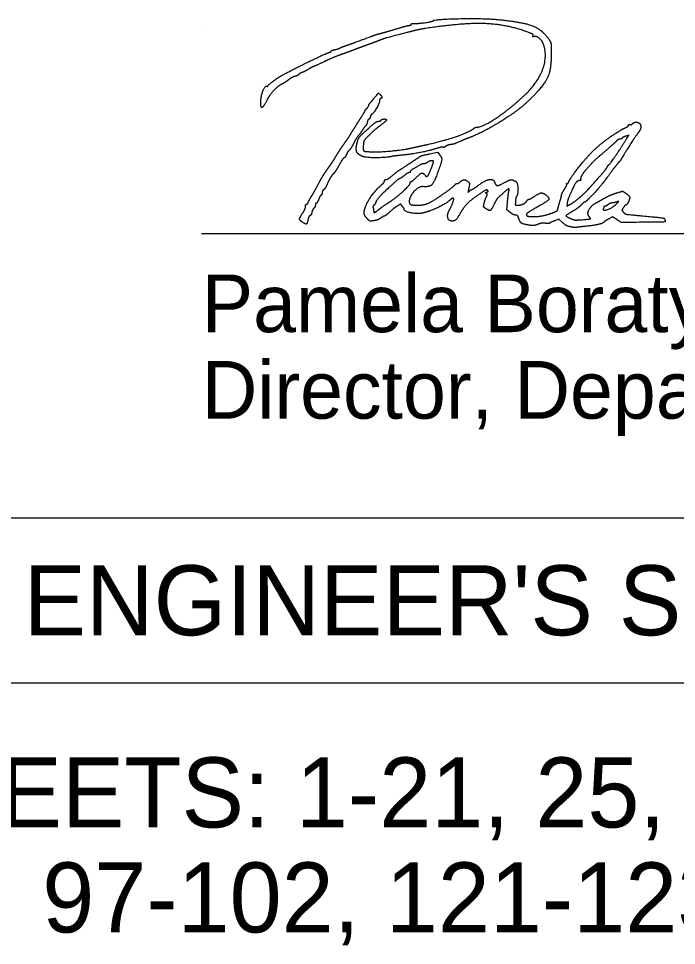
# Model space of a CAD drawing. Extents: x -21.9 to 47.3, y 14.1 to 48.7.
# Drawn here: x 24.055 to 25.653, y 33.195 to 35.446 of the extents above; entities that cross this region are included whole.
import ezdxf

# ---------------------------------------------------------------- set-up
doc = ezdxf.new("R2010")
doc.units = 0
for name, color, linetype in [('GM_X_City_Street', 7, 'Continuous'), ('SH_Data', 7, 'Continuous'), ('SH_Text', 7, 'Continuous')]:
    doc.layers.add(name, color=color, linetype=linetype)

msp = doc.modelspace()

# ---------------------------------------------------------------- linework, layer by layer
at = {"layer": 'GM_X_City_Street'}
for points in [[(25.5318, 35.1539), (25.5372, 35.1628), (25.5298, 35.1602)], [(25.0545, 35.1177), (25.0725, 35.1218), (25.0772, 35.1156)], [(25.2494, 34.9749), (25.2411, 34.9812), (25.2426, 34.9983)], [(25.3874, 34.9969), (25.3864, 34.9904), (25.3951, 34.9949)], [(25.3764, 34.9506), (25.3672, 34.9589), (25.3567, 34.9548)], [(25.5083, 34.9576), (25.4976, 34.9644), (25.4892, 34.9599)]]:
    msp.add_lwpolyline(points, dxfattribs=at)
for points in [[(24.9721, 35.4207), (24.9882, 35.4255), (25.0031, 35.4294), (25.0051, 35.4294)], [(25.0051, 35.4294), (25.0072, 35.4294), (25.0089, 35.4305), (25.0089, 35.4318)], [(25.0089, 35.4318), (25.0089, 35.4332), (25.0129, 35.4342), (25.0179, 35.4341)], [(25.0179, 35.4341), (25.0275, 35.4338), (25.0585, 35.4382), (25.0619, 35.4403)], [(25.2926, 35.4126), (25.242, 35.4316), (25.1341, 35.4356), (25.0437, 35.4218)], [(25.0619, 35.4403), (25.0687, 35.4445), (25.1857, 35.4468), (25.2201, 35.4434)], [(25.2201, 35.4434), (25.2794, 35.4375), (25.3269, 35.4193), (25.3427, 35.3962)], [(24.9093, 35.4017), (24.9172, 35.4047), (24.928, 35.4082), (24.9333, 35.4096)], [(24.9333, 35.4096), (24.9386, 35.4109), (24.9561, 35.4159), (24.9721, 35.4207)], [(24.9993, 35.4121), (24.9483, 35.3989), (24.944, 35.3977), (24.9333, 35.3934)], [(25.0437, 35.4218), (25.0345, 35.4204), (25.0145, 35.4161), (24.9993, 35.4121)], [(25.3049, 35.404), (25.3059, 35.4065), (25.3024, 35.4089), (25.2926, 35.4126)], [(25.3073, 35.4019), (25.3047, 35.4009), (25.304, 35.4016), (25.3049, 35.404)], [(25.3307, 35.382), (25.3274, 35.3918), (25.313, 35.4041), (25.3073, 35.4019)], [(24.8349, 35.374), (24.8362, 35.3749), (24.8443, 35.3782), (24.8529, 35.3811)], [(24.8529, 35.3811), (24.8676, 35.3862), (24.8741, 35.3886), (24.9093, 35.4017)], [(24.9105, 35.3849), (24.9006, 35.3813), (24.8855, 35.3757), (24.8769, 35.3725)], [(24.9333, 35.3934), (24.9307, 35.3923), (24.9204, 35.3885), (24.9105, 35.3849)], [(25.2852, 35.2608), (25.3161, 35.2902), (25.34, 35.3538), (25.3307, 35.382)], [(25.3427, 35.3962), (25.3476, 35.389), (25.3486, 35.3846), (25.3489, 35.3668)], [(24.6969, 35.309), (24.7271, 35.3252), (24.8007, 35.3608), (24.8091, 35.3633)], [(24.8409, 35.3593), (24.8297, 35.3554), (24.8093, 35.3468), (24.7957, 35.3403)], [(24.8091, 35.3633), (24.8121, 35.3642), (24.8145, 35.3658), (24.8145, 35.3668)], [(24.8145, 35.3668), (24.8145, 35.3679), (24.8185, 35.3696), (24.8235, 35.3705)], [(24.8235, 35.3705), (24.8284, 35.3714), (24.8336, 35.373), (24.8349, 35.374)], [(24.8769, 35.3725), (24.8683, 35.3692), (24.8521, 35.3633), (24.8409, 35.3593)], [(25.3489, 35.3668), (25.3496, 35.326), (25.3335, 35.2863), (25.3041, 35.2564)], [(24.7957, 35.3403), (24.782, 35.3338), (24.7704, 35.3286), (24.7698, 35.3286)], [(24.745, 35.3154), (24.7418, 35.3144), (24.7376, 35.312), (24.7358, 35.3102)], [(24.7598, 35.3229), (24.7549, 35.3198), (24.7482, 35.3164), (24.745, 35.3154)], [(24.7698, 35.3286), (24.7693, 35.3286), (24.7648, 35.326), (24.7598, 35.3229)], [(24.6609, 35.2823), (24.6609, 35.2845), (24.6863, 35.3033), (24.6969, 35.309)], [(24.7113, 35.2973), (24.7067, 35.2937), (24.6995, 35.2891), (24.6954, 35.287)], [(24.7261, 35.3054), (24.7226, 35.3045), (24.7159, 35.3009), (24.7113, 35.2973)], [(24.7358, 35.3102), (24.734, 35.3084), (24.7297, 35.3063), (24.7261, 35.3054)], [(24.6437, 35.2445), (24.6438, 35.2577), (24.6545, 35.2842), (24.6586, 35.2817)], [(24.6586, 35.2817), (24.6599, 35.2809), (24.6609, 35.2812), (24.6609, 35.2823)], [(24.6954, 35.287), (24.685, 35.2817), (24.6651, 35.2608), (24.6589, 35.2487)], [(24.6451, 35.2308), (24.6443, 35.2316), (24.6437, 35.2377), (24.6437, 35.2445)], [(24.6589, 35.2487), (24.6522, 35.2358), (24.6469, 35.2289), (24.6451, 35.2308)], [(24.9111, 35.2434), (24.9296, 35.2655), (24.9289, 35.265), (24.933, 35.2616)], [(24.9321, 35.2467), (24.9321, 35.2411), (24.9162, 35.2134), (24.913, 35.2134)], [(24.9345, 35.2518), (24.9332, 35.2518), (24.9321, 35.2495), (24.9321, 35.2467)], [(24.933, 35.2616), (24.9373, 35.258), (24.9382, 35.2518), (24.9345, 35.2518)], [(25.1685, 35.1822), (25.1826, 35.1822), (25.2507, 35.2281), (25.2852, 35.2608)], [(25.3041, 35.2564), (25.2855, 35.2375), (25.2531, 35.2126), (25.2226, 35.1938)], [(24.8881, 35.2073), (24.8937, 35.2159), (24.8977, 35.223), (24.8971, 35.223)], [(24.8971, 35.223), (24.8966, 35.223), (24.8983, 35.2251), (24.9009, 35.2278)], [(24.9009, 35.2278), (24.9035, 35.2304), (24.9057, 35.2335), (24.9057, 35.2347)], [(24.9057, 35.2347), (24.9057, 35.236), (24.9081, 35.2398), (24.9111, 35.2434)], [(24.8661, 35.1723), (24.8727, 35.1829), (24.8826, 35.1987), (24.8881, 35.2073)], [(24.9058, 35.2014), (24.9047, 35.2014), (24.903, 35.1981), (24.9021, 35.1942)], [(24.9095, 35.2074), (24.9087, 35.2041), (24.907, 35.2014), (24.9058, 35.2014)], [(24.913, 35.2134), (24.9119, 35.2134), (24.9103, 35.2107), (24.9095, 35.2074)], [(24.9357, 35.199), (24.9375, 35.2019), (24.9489, 35.2022), (24.9489, 35.1993)], [(24.8982, 35.1856), (24.8969, 35.1848), (24.8931, 35.1796), (24.8897, 35.1741)], [(24.8973, 35.1724), (24.913, 35.187), (24.9258, 35.1966), (24.9297, 35.1966)], [(24.9021, 35.1942), (24.9012, 35.1902), (24.8995, 35.1864), (24.8982, 35.1856)], [(24.9339, 35.1862), (24.9256, 35.1801), (24.9131, 35.1692), (24.9061, 35.1621)], [(24.9297, 35.1966), (24.9322, 35.1966), (24.9349, 35.1976), (24.9357, 35.199)], [(24.9489, 35.1993), (24.9489, 35.1982), (24.9421, 35.1923), (24.9339, 35.1862)], [(25.0485, 35.1402), (25.0854, 35.1484), (25.1517, 35.1713), (25.1603, 35.1788)], [(25.2226, 35.1938), (25.2035, 35.1819), (25.1622, 35.1609), (25.1481, 35.1558)], [(25.1603, 35.1788), (25.1624, 35.1807), (25.1661, 35.1822), (25.1685, 35.1822)], [(25.5001, 35.1638), (25.5191, 35.176), (25.5209, 35.1771), (25.5291, 35.1808)], [(25.5291, 35.1808), (25.5334, 35.1827), (25.5369, 35.1856), (25.5369, 35.1871)], [(25.5369, 35.1871), (25.5369, 35.1886), (25.5384, 35.1893), (25.5403, 35.1886)], [(25.5403, 35.1886), (25.5422, 35.1878), (25.545, 35.1888), (25.5466, 35.1907)], [(25.5466, 35.1907), (25.5482, 35.1926), (25.5519, 35.1942), (25.5548, 35.1942)], [(25.5548, 35.1942), (25.5643, 35.1942), (25.568, 35.1781), (25.5606, 35.1691)], [(24.8443, 35.1393), (24.8497, 35.1468), (24.8595, 35.1616), (24.8661, 35.1723)], [(24.8806, 35.1617), (24.8789, 35.1604), (24.8742, 35.1528), (24.8702, 35.1448)], [(24.876, 35.1378), (24.8787, 35.1508), (24.8849, 35.1608), (24.8973, 35.1724)], [(24.8897, 35.1741), (24.8863, 35.1686), (24.8822, 35.1631), (24.8806, 35.1617)], [(24.9061, 35.1621), (24.8954, 35.1511), (24.8932, 35.1474), (24.8927, 35.1392)], [(25.1481, 35.1558), (25.1435, 35.1542), (25.1364, 35.1514), (25.1325, 35.1496)], [(25.4055, 35.0712), (25.4278, 35.1021), (25.4728, 35.1461), (25.5001, 35.1638)], [(25.5212, 35.1555), (25.5204, 35.1543), (25.518, 35.1534), (25.5158, 35.1534)], [(25.5606, 35.1691), (25.5564, 35.1641), (25.5236, 35.1137), (25.5204, 35.1075)], [(25.5298, 35.1602), (25.5258, 35.1588), (25.5219, 35.1567), (25.5212, 35.1555)], [(24.8276, 35.1138), (24.8315, 35.1204), (24.839, 35.1319), (24.8443, 35.1393)], [(24.8702, 35.1448), (24.8662, 35.1368), (24.8611, 35.1288), (24.859, 35.127)], [(24.8913, 35.1109), (24.8809, 35.1148), (24.8737, 35.1273), (24.876, 35.1378)], [(24.8927, 35.1392), (24.8918, 35.1258), (24.8959, 35.1229), (24.9165, 35.1223)], [(24.9165, 35.1223), (24.9358, 35.1218), (24.9936, 35.1279), (25.0149, 35.1327)], [(25.0149, 35.1327), (25.0228, 35.1345), (25.0379, 35.1379), (25.0485, 35.1402)], [(25.0863, 35.1335), (25.0846, 35.1341), (25.0765, 35.1324), (25.0683, 35.1297)], [(25.0931, 35.1357), (25.091, 35.1339), (25.0879, 35.1329), (25.0863, 35.1335)], [(25.1039, 35.1397), (25.1, 35.1393), (25.0952, 35.1375), (25.0931, 35.1357)], [(25.1325, 35.1496), (25.1154, 35.1422), (25.1105, 35.1405), (25.1039, 35.1397)], [(25.507, 35.148), (25.5043, 35.145), (25.4918, 35.1339), (25.4793, 35.1234)], [(25.489, 35.091), (25.4918, 35.0929), (25.52, 35.1344), (25.5318, 35.1539)], [(25.5158, 35.1534), (25.5136, 35.1534), (25.5097, 35.1509), (25.507, 35.148)], [(24.8146, 35.0931), (24.8179, 35.0979), (24.8238, 35.1072), (24.8276, 35.1138)], [(24.8517, 35.1157), (24.8498, 35.1113), (24.8473, 35.1078), (24.846, 35.1078)], [(24.859, 35.127), (24.8568, 35.1252), (24.8535, 35.1201), (24.8517, 35.1157)], [(24.9625, 35.1111), (24.9488, 35.108), (24.8993, 35.1079), (24.8913, 35.1109)], [(24.9829, 35.1137), (24.9746, 35.1129), (24.9654, 35.1117), (24.9625, 35.1111)], [(25.0683, 35.1297), (25.0518, 35.1245), (25.0067, 35.116), (24.9829, 35.1137)], [(25.0005, 35.0913), (25.0322, 35.1123), (25.0335, 35.113), (25.0545, 35.1177)], [(25.0772, 35.1156), (25.0838, 35.1068), (25.0836, 35.102), (25.0759, 35.0794)], [(25.4793, 35.1234), (25.4597, 35.1069), (25.448, 35.0955), (25.4313, 35.0766)], [(24.801, 35.0739), (24.8051, 35.0797), (24.8112, 35.0884), (24.8146, 35.0931)], [(24.8339, 35.0902), (24.8286, 35.0805), (24.8219, 35.0705), (24.8191, 35.068)], [(24.846, 35.1078), (24.8447, 35.1078), (24.8393, 35.0998), (24.8339, 35.0902)], [(24.9613, 35.0634), (24.975, 35.0744), (24.973, 35.073), (25.0005, 35.0913)], [(25.0302, 35.0902), (25.0158, 35.0823), (25.0065, 35.0759), (25.0065, 35.0739)], [(25.0399, 35.0934), (25.0377, 35.0934), (25.0333, 35.0919), (25.0302, 35.0902)], [(25.0486, 35.0969), (25.0461, 35.0949), (25.0421, 35.0934), (25.0399, 35.0934)], [(25.0471, 35.0622), (25.0489, 35.0622), (25.0587, 35.0833), (25.0618, 35.094)], [(25.0585, 35.1005), (25.0557, 35.1004), (25.0512, 35.0988), (25.0486, 35.0969)], [(25.0618, 35.094), (25.0635, 35.0997), (25.0631, 35.1005), (25.0585, 35.1005)], [(25.4851, 35.0858), (25.4863, 35.088), (25.4881, 35.0903), (25.489, 35.091)], [(25.5118, 35.0953), (25.5088, 35.0921), (25.4999, 35.0808), (25.492, 35.0701)], [(25.5204, 35.1075), (25.5187, 35.104), (25.5148, 35.0986), (25.5118, 35.0953)], [(24.7821, 35.0418), (24.7884, 35.0536), (24.7969, 35.0681), (24.801, 35.0739)], [(24.8191, 35.068), (24.8162, 35.0654), (24.8107, 35.0563), (24.8068, 35.0478)], [(24.9921, 35.0646), (24.9871, 35.0606), (24.9821, 35.0573), (24.981, 35.0573)], [(25.0038, 35.0718), (25.0024, 35.0718), (24.9971, 35.0685), (24.9921, 35.0646)], [(25.0065, 35.0739), (25.0065, 35.0727), (25.0053, 35.0718), (25.0038, 35.0718)], [(25.0209, 35.0598), (25.031, 35.0699), (25.0376, 35.0717), (25.0425, 35.0658)], [(25.0759, 35.0794), (25.0656, 35.0495), (25.0537, 35.0364), (25.0377, 35.0378)], [(25.0425, 35.0658), (25.0441, 35.0638), (25.0462, 35.0622), (25.0471, 35.0622)], [(25.3905, 35.0479), (25.3905, 35.0493), (25.3972, 35.0598), (25.4055, 35.0712)], [(25.4313, 35.0766), (25.4255, 35.07), (25.4192, 35.0571), (25.4206, 35.0547)], [(25.4538, 35.048), (25.4691, 35.0651), (25.4827, 35.0815), (25.4851, 35.0858)], [(25.492, 35.0701), (25.4841, 35.0595), (25.4765, 35.0493), (25.475, 35.0475)], [(24.8068, 35.0478), (24.8029, 35.0392), (24.7981, 35.0313), (24.7963, 35.0302)], [(24.9006, 34.9955), (24.9051, 35.0059), (24.9283, 35.0354), (24.9387, 35.0437)], [(24.9387, 35.0437), (24.9417, 35.0461), (24.9441, 35.0496), (24.9441, 35.0515)], [(24.9441, 35.0515), (24.9441, 35.0534), (24.9456, 35.055), (24.9475, 35.055)], [(24.981, 35.0573), (24.9791, 35.0573), (24.9706, 35.0501), (24.9453, 35.0268)], [(24.9475, 35.055), (24.9493, 35.055), (24.9555, 35.0587), (24.9613, 35.0634)], [(24.9604, 35.0036), (24.976, 35.014), (25.0065, 35.0427), (25.0065, 35.047)], [(25.0065, 35.047), (25.0065, 35.0487), (25.0076, 35.0502), (25.0089, 35.0502)], [(25.0089, 35.0502), (25.0102, 35.0502), (25.0156, 35.0545), (25.0209, 35.0598)], [(25.0725, 35.0105), (25.0911, 35.0228), (25.1135, 35.0395), (25.1152, 35.0423)], [(25.1152, 35.0423), (25.1163, 35.044), (25.1186, 35.0454), (25.1204, 35.0454)], [(25.1204, 35.0454), (25.1223, 35.0454), (25.1255, 35.0471), (25.1277, 35.0493)], [(25.1277, 35.0493), (25.1326, 35.0542), (25.1426, 35.0543), (25.1475, 35.0493)], [(25.1475, 35.0493), (25.1507, 35.0462), (25.1509, 35.0437), (25.1488, 35.0346)], [(25.1657, 35.0367), (25.1859, 35.0519), (25.2086, 35.0575), (25.2116, 35.048)], [(25.2116, 35.048), (25.214, 35.0404), (25.2221, 35.0403), (25.2354, 35.0476)], [(25.2354, 35.0476), (25.2474, 35.0543), (25.2546, 35.055), (25.2628, 35.0504)], [(25.2628, 35.0504), (25.2672, 35.0479), (25.2689, 35.0199), (25.265, 35.0147)], [(25.3807, 35.0311), (25.3846, 35.0373), (25.3871, 35.0431), (25.3863, 35.0439)], [(25.3863, 35.0439), (25.3855, 35.0447), (25.3862, 35.0454), (25.3877, 35.0454)], [(25.3877, 35.0454), (25.3892, 35.0454), (25.3905, 35.0465), (25.3905, 35.0479)], [(25.4184, 35.0526), (25.412, 35.0526), (25.4025, 35.0374), (25.3904, 35.0082)], [(25.4206, 35.0547), (25.4214, 35.0535), (25.4204, 35.0526), (25.4184, 35.0526)], [(25.4382, 35.0305), (25.4413, 35.0341), (25.4484, 35.0419), (25.4538, 35.048)], [(25.475, 35.0475), (25.4617, 35.031), (25.4572, 35.0259), (25.4453, 35.0137)], [(24.7667, 35.0142), (24.7689, 35.0175), (24.7759, 35.0299), (24.7821, 35.0418)], [(24.7929, 35.0238), (24.7929, 35.0213), (24.7918, 35.0185), (24.7904, 35.0177)], [(24.7963, 35.0302), (24.7944, 35.0292), (24.7929, 35.0263), (24.7929, 35.0238)], [(24.9453, 35.0268), (24.9362, 35.0184), (24.9225, 35.0014), (24.9225, 34.9984)], [(25.0377, 35.0378), (25.0273, 35.0387), (25.0041, 35.0133), (25.0041, 35.001)], [(25.1741, 35.0194), (25.1544, 35.006), (25.1372, 34.9889), (25.1289, 34.9746)], [(25.1488, 35.0346), (25.1465, 35.0243), (25.1466, 35.0238), (25.1504, 35.0273)], [(25.1504, 35.0273), (25.1526, 35.0293), (25.1553, 35.031), (25.1562, 35.031)], [(25.1562, 35.031), (25.1572, 35.031), (25.1615, 35.0335), (25.1657, 35.0367)], [(25.1943, 35.0289), (25.1925, 35.0307), (25.1866, 35.0279), (25.1741, 35.0194)], [(25.1915, 35.0212), (25.1893, 35.0226), (25.1896, 35.0235), (25.1927, 35.0247)], [(25.1908, 35.0114), (25.1937, 35.0177), (25.1938, 35.0198), (25.1915, 35.0212)], [(25.1927, 35.0247), (25.1957, 35.0258), (25.1962, 35.0271), (25.1943, 35.0289)], [(25.2354, 35.0248), (25.2195, 35.0108), (25.2158, 35.0064), (25.2103, 34.995)], [(25.2455, 35.0232), (25.2474, 35.0326), (25.2447, 35.033), (25.2354, 35.0248)], [(25.2426, 34.9983), (25.2434, 35.0077), (25.2447, 35.0189), (25.2455, 35.0232)], [(25.3081, 35.0142), (25.321, 35.0224), (25.3286, 35.0232), (25.3363, 35.0171)], [(25.3737, 35.0163), (25.3737, 35.0181), (25.3769, 35.0248), (25.3807, 35.0311)], [(25.4181, 35.0117), (25.426, 35.0185), (25.4351, 35.027), (25.4382, 35.0305)], [(25.4781, 35.0097), (25.486, 35.0142), (25.4992, 35.0199), (25.5074, 35.0224)], [(25.5074, 35.0224), (25.5215, 35.0266), (25.5226, 35.0266), (25.5285, 35.0228)], [(25.5285, 35.0228), (25.5381, 35.0165), (25.5405, 35.0091), (25.5359, 35.0001)], [(24.7545, 34.995), (24.7559, 34.995), (24.7583, 34.9979), (24.7598, 35.0016)], [(24.7598, 35.0016), (24.7614, 35.0052), (24.7645, 35.0109), (24.7667, 35.0142)], [(24.7782, 34.9974), (24.7771, 34.9974), (24.7761, 34.9953), (24.7761, 34.9928)], [(24.7841, 35.0067), (24.7821, 35.0016), (24.7794, 34.9974), (24.7782, 34.9974)], [(24.7904, 35.0177), (24.789, 35.0168), (24.7862, 35.0119), (24.7841, 35.0067)], [(24.9225, 34.9984), (24.9225, 34.9976), (24.9208, 34.9953), (24.9188, 34.9933)], [(24.9289, 34.9812), (24.9364, 34.9873), (24.9417, 34.9911), (24.9604, 35.0036)], [(25.0041, 35.001), (25.0041, 34.9959), (25.0119, 34.9926), (25.024, 34.9926)], [(25.024, 34.9926), (25.0371, 34.9926), (25.0562, 34.9996), (25.0725, 35.0105)], [(25.1045, 35.0063), (25.0949, 34.9972), (25.0562, 34.9784), (25.0377, 34.9739)], [(25.1015, 34.9806), (25.1056, 34.9882), (25.1121, 35.0045), (25.1121, 35.0072)], [(25.1121, 35.0072), (25.1121, 35.0103), (25.1081, 35.0098), (25.1045, 35.0063)], [(25.1857, 34.9958), (25.1865, 34.9999), (25.1888, 35.007), (25.1908, 35.0114)], [(25.262, 35.0021), (25.2615, 34.9946), (25.2622, 34.9926), (25.2654, 34.9926)], [(25.265, 35.0147), (25.2637, 35.0131), (25.2624, 35.0074), (25.262, 35.0021)], [(25.2654, 34.9926), (25.2737, 34.9926), (25.2857, 34.9974), (25.289, 35.0021)], [(25.289, 35.0021), (25.2908, 35.0048), (25.2933, 35.007), (25.2945, 35.007)], [(25.2945, 35.007), (25.2957, 35.007), (25.3018, 35.0102), (25.3081, 35.0142)], [(25.3363, 35.0171), (25.346, 35.0095), (25.3391, 35.0016), (25.3076, 34.9839)], [(25.3654, 34.9851), (25.3661, 34.9885), (25.3683, 34.9962), (25.3702, 35.0022)], [(25.3702, 35.0022), (25.3721, 35.0081), (25.3737, 35.0145), (25.3737, 35.0163)], [(25.3904, 35.0082), (25.3893, 35.0055), (25.388, 35.0004), (25.3874, 34.9969)], [(25.3951, 34.9949), (25.3998, 34.9973), (25.4102, 35.0049), (25.4181, 35.0117)], [(25.4297, 34.9998), (25.4286, 34.9998), (25.4247, 34.9966), (25.4211, 34.9928)], [(25.4453, 35.0137), (25.4378, 35.006), (25.4308, 34.9998), (25.4297, 34.9998)], [(25.4415, 34.9643), (25.4354, 34.9717), (25.4452, 34.9915), (25.4585, 34.9987)], [(25.4585, 34.9987), (25.4614, 35.0002), (25.4702, 35.0052), (25.4781, 35.0097)], [(25.4975, 34.9983), (25.4936, 34.9978), (25.4887, 34.9957), (25.4865, 34.9937)], [(25.5093, 35.001), (25.5067, 35), (25.5013, 34.9988), (25.4975, 34.9983)], [(25.5069, 34.9955), (25.5124, 35.0011), (25.513, 35.0024), (25.5093, 35.001)], [(25.5359, 35.0001), (25.5337, 34.9959), (25.531, 34.9926), (25.5299, 34.9926)], [(24.7446, 34.9514), (24.7376, 34.9562), (24.7381, 34.9629), (24.7463, 34.9751)], [(24.7463, 34.9751), (24.7495, 34.9798), (24.7521, 34.9862), (24.7521, 34.9893)], [(24.7521, 34.9893), (24.7521, 34.9924), (24.7532, 34.995), (24.7545, 34.995)], [(24.7676, 34.9754), (24.7668, 34.9715), (24.7646, 34.9677), (24.7629, 34.967)], [(24.7727, 34.9855), (24.7708, 34.9839), (24.7685, 34.9794), (24.7676, 34.9754)], [(24.7761, 34.9928), (24.7761, 34.9904), (24.7745, 34.9871), (24.7727, 34.9855)], [(24.9023, 34.9598), (24.8947, 34.9674), (24.8941, 34.9802), (24.9006, 34.9955)], [(24.9188, 34.9933), (24.9167, 34.9912), (24.9156, 34.988), (24.9164, 34.986)], [(24.9164, 34.986), (24.9171, 34.9841), (24.9177, 34.981), (24.9177, 34.9792)], [(24.9177, 34.9792), (24.9177, 34.9743), (24.9211, 34.9749), (24.9289, 34.9812)], [(24.9762, 34.9914), (24.968, 34.986), (24.9654, 34.984), (24.9542, 34.974)], [(24.9875, 34.99), (24.983, 34.9958), (24.983, 34.9958), (24.9762, 34.9914)], [(24.992, 34.9826), (24.992, 34.9835), (24.99, 34.9868), (24.9875, 34.99)], [(25.0377, 34.9739), (25.0248, 34.9708), (24.9922, 34.977), (24.992, 34.9826)], [(25.1082, 34.9542), (25.0998, 34.9542), (25.0958, 34.97), (25.1015, 34.9806)], [(25.1289, 34.9746), (25.1207, 34.9604), (25.1143, 34.9542), (25.1082, 34.9542)], [(25.1903, 34.9842), (25.1853, 34.9875), (25.1845, 34.9895), (25.1857, 34.9958)], [(25.2103, 34.995), (25.2036, 34.9813), (25.1988, 34.9787), (25.1903, 34.9842)], [(25.2624, 34.9686), (25.2599, 34.9686), (25.254, 34.9714), (25.2494, 34.9749)], [(25.3076, 34.9839), (25.2943, 34.9764), (25.2881, 34.9716), (25.289, 34.9694)], [(25.3029, 34.9651), (25.3134, 34.9645), (25.3396, 34.9694), (25.3527, 34.9744)], [(25.3527, 34.9744), (25.3615, 34.9778), (25.3645, 34.9803), (25.3654, 34.9851)], [(25.4031, 34.9792), (25.3852, 34.9688), (25.3842, 34.9655), (25.3971, 34.96)], [(25.4211, 34.9928), (25.4175, 34.989), (25.4094, 34.9829), (25.4031, 34.9792)], [(25.4755, 34.9844), (25.473, 34.9779), (25.4984, 34.9868), (25.5069, 34.9955)], [(25.4769, 34.9891), (25.4769, 34.9886), (25.4763, 34.9865), (25.4755, 34.9844)], [(25.4797, 34.9902), (25.4782, 34.9902), (25.4769, 34.9897), (25.4769, 34.9891)], [(25.4865, 34.9937), (25.4843, 34.9918), (25.4813, 34.9902), (25.4797, 34.9902)], [(25.524, 34.9867), (25.5205, 34.9814), (25.5206, 34.9805), (25.5244, 34.9758)], [(25.5299, 34.9926), (25.5288, 34.9926), (25.5261, 34.9899), (25.524, 34.9867)], [(25.5244, 34.9758), (25.528, 34.9713), (25.533, 34.9703), (25.5669, 34.9671)], [(24.7583, 34.9578), (24.7564, 34.9481), (24.7522, 34.9461), (24.7446, 34.9514)], [(24.7629, 34.967), (24.7612, 34.9664), (24.7591, 34.9622), (24.7583, 34.9578)], [(24.9185, 34.9551), (24.9098, 34.9538), (24.9076, 34.9544), (24.9023, 34.9598)], [(24.935, 34.9614), (24.9314, 34.9588), (24.924, 34.956), (24.9185, 34.9551)], [(24.9435, 34.9662), (24.9424, 34.9662), (24.9386, 34.964), (24.935, 34.9614)], [(24.9542, 34.974), (24.9494, 34.9697), (24.9446, 34.9662), (24.9435, 34.9662)], [(25.27, 34.9608), (25.2681, 34.9659), (25.2656, 34.9686), (25.2624, 34.9686)], [(25.2953, 34.9442), (25.2803, 34.9466), (25.2735, 34.9511), (25.27, 34.9608)], [(25.289, 34.9694), (25.2903, 34.966), (25.291, 34.9658), (25.3029, 34.9651)], [(25.3567, 34.9548), (25.3509, 34.9525), (25.3458, 34.9499), (25.3454, 34.9491)], [(25.3971, 34.96), (25.4039, 34.957), (25.4104, 34.9565), (25.4239, 34.9575)], [(25.4239, 34.9575), (25.4434, 34.9591), (25.4452, 34.9598), (25.4415, 34.9643)], [(25.4775, 34.952), (25.4738, 34.9483), (25.4523, 34.9434), (25.4289, 34.941)], [(25.4892, 34.9599), (25.4846, 34.9574), (25.4794, 34.9539), (25.4775, 34.952)], [(25.5549, 34.9511), (25.5192, 34.9508), (25.5188, 34.9508), (25.5083, 34.9576)], [(25.6252, 34.9562), (25.626, 34.952), (25.624, 34.9519), (25.5549, 34.9511)], [(25.5669, 34.9671), (25.616, 34.9626), (25.6243, 34.961), (25.6252, 34.9562)], [(25.3164, 34.9462), (25.3094, 34.9434), (25.3039, 34.9429), (25.2953, 34.9442)], [(25.3353, 34.9487), (25.3295, 34.9495), (25.3222, 34.9485), (25.3164, 34.9462)], [(25.3454, 34.9491), (25.345, 34.9482), (25.3404, 34.948), (25.3353, 34.9487)], [(25.391, 34.9411), (25.388, 34.9417), (25.3814, 34.946), (25.3764, 34.9506)], [(25.4013, 34.939), (25.3987, 34.9395), (25.394, 34.9405), (25.391, 34.9411)], [(25.4097, 34.9387), (25.4077, 34.9383), (25.4039, 34.9384), (25.4013, 34.939)], [(25.4289, 34.941), (25.4203, 34.9401), (25.4117, 34.9391), (25.4097, 34.9387)]]:
    msp.add_open_spline(points, degree=2, dxfattribs=at)
at = {"layer": 'SH_Data'}
for p, q in [((24.5, 35.4244), (24.5, 35.4244)), ((24.5, 34.9244), (28, 34.9244)), ((23.6, 34.2334), (26.4, 34.2334)), ((23.6, 33.8334), (26.4, 33.8334))]:
    msp.add_line(p, q, dxfattribs=at)

# ---------------------------------------------------------------- texts
msp.add_text("ENGINEER'S SEAL", height=0.17, dxfattribs=at).set_placement((24.0676, 33.9484))
at = {"layer": 'SH_Text'}
for s, height, p in [('Pamela Boratyn', 0.14, (24.5, 34.6844)), ('Director, Department of Transportation', 0.14, (24.5, 34.4744)), ('SHEETS: 1-21, 25, 27-86,', 0.17, (23.6931, 33.4819)), ('97-102, 121-123', 0.17, (24.1129, 33.2269))]:
    msp.add_text(s, height=height, dxfattribs=at).set_placement(p)

doc.saveas('drawing.dxf')
